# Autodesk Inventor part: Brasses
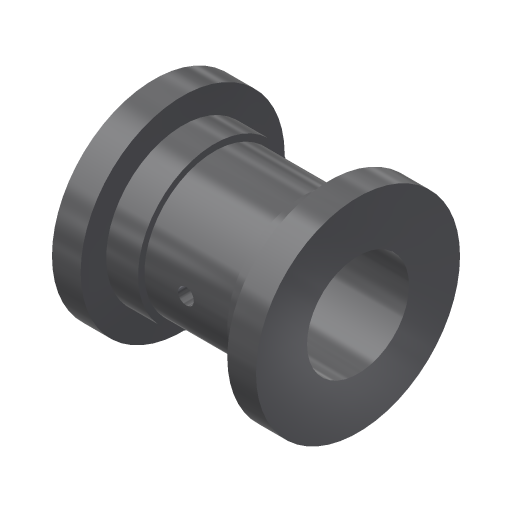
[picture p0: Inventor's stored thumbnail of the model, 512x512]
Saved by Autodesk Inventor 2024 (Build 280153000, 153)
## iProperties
Created: 2009-04
Part Number: Brasses
Document SubType Name: Modeling
Designer: Sham
Density: 7.85 g/cm^3
Material: Steel
Appearance: Smooth - Medium Gray
Author: Sham
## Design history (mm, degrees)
sketch "Sketch1"
  geometry: L1 (0, 32)-(9, 32); L2 (0, 16)-(64, 16); L3 (64, 32)-(55, 32); L4 (55, 32)-(55, 24); L5 (55, 24)-(47, 24); L6 (19, 22)-(47, 22); L7 (47, 24)-(47, 22); L8 (19, 22)-(19, 24); L9 (19, 24)-(9, 24); L10 (9, 24)-(9, 32); L11 (0, 32)-(0, 16); L12 (64, 32)-(64, 16); L13 (-12.8, 0)-(76.8, 0) reference; 1 further point
  constraints: 24 end point, 7 parallel, 4 perpendicular, 1 collinear, 1 horizontal, 1 vertical alignment, 1 other
  dimensions: "d0" = 9 distance of L1.start L1.end; "d2" = 16 distance from line of L2 point (0, 0); "d3" = 64 distance of L2.start L2.end; "d4" = 24 distance from line of point (0, 0) L5; "d5" = 28 distance of L6.start L6.end; "d6" = 22 distance from line of point (0, 0) L6; "d7" = 8 distance of L4.end L5.end
revolve "Revolution2" sketch "Sketch1" stored, may be unused: angle "d16" = 90 deg
workplane "Work Plane2"
sketch "Sketch4"
  geometry: L1 (-32, 45.783)-(-32, -45.783); L2 (-64, 32)-(-64, -32) reference; L3 (0, 0)-(-64, 0); C1 r 4 at (-32, 0); 1 further point
  constraints: 4 end point, 2 midpoint, 1 centre point, 1 coincident, 1 horizontal, 1 vertical
  dimensions: "d18" = 32 distance between parallel lines of L1 L2; "d19" = 8 diameter of C1
extrude "Extrusion3" join sketch "Sketch4" stored distance "d20" = 0; taper "d21" = 0 deg
sketch "Sketch5"
  geometry: C1 r 2.5 at (0, 0); 1 further point
  constraints: 1 centre point
  dimensions: "d22" = 5 diameter of C1
extrude "Extrusion4" cut sketch "Sketch5" distance "d23" = 111; taper "d24" = 0 deg
body "Solid2"
